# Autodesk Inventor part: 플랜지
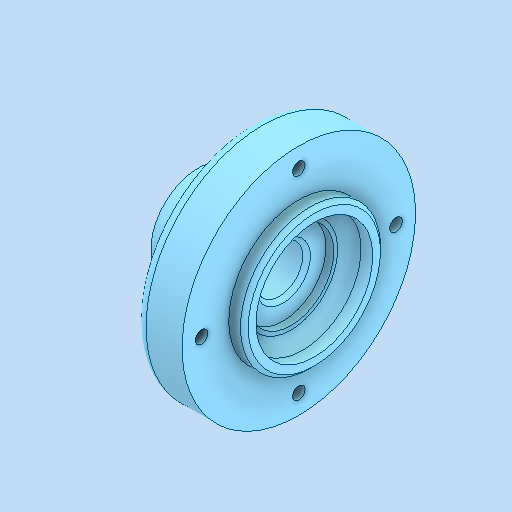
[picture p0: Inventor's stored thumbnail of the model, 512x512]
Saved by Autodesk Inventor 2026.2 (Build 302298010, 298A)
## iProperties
Created: 2026-03
Part Number: 플랜지
Material: 강철, 연강
Document SubType Name: Modeling
Designer: PC-2-03
Density: 7.85 g/cm^3
Appearance: 기본값
Author: jhkim
Sending System: Autodesk Inventor 2026
Preprocessor: ST-DEVELOPER v20.1
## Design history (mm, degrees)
feature "솔리드1"
node "솔리드2"
